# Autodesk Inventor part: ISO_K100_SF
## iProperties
Created: 2005-11
Part Number: ISO_K100_SF
Material: 1.4301 X5CrNi10-10 A2
Description: Flansch DN100 ISO-K
Document SubType Name: Modellieren
Designer: Mittelmeyer
Manufacturer: Standard
Standards Organization: Custom
Author: Mittelmeyer
Comments: LEYBOLD
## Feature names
1. Extrusion2
2. Extrusion3
3. Extrusion4
4. Drehung1 [Revolution]
5. Bohrung1 [Hole]
6. Extrusion5
